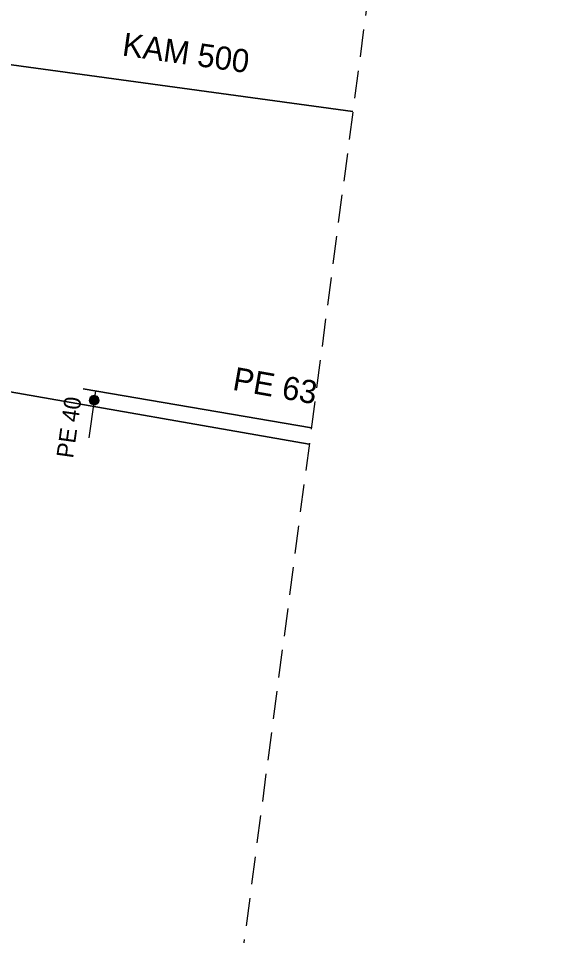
# Model space of a CAD drawing. Extents: x -867121 to -866743, y -1014362 to -1014088.
# Drawn here: x -866767.71 to -866742.8, y -1014225.88 to -1014182.35 of the extents above; entities that cross this region are included whole.
import ezdxf

# ---------------------------------------------------------------- set-up
doc = ezdxf.new("R2010")
doc.units = 0
doc.header["$LTSCALE"] = 0.44
doc.linetypes.add('MEDIUM_DASHED', pattern=[4.5, 3, -1.5])
for name, color, linetype, lineweight in [('1', 7, 'Continuous', 35), ('12', 7, 'Continuous', 13), ('21', 7, 'Continuous', 35), ('3', 7, 'Continuous', 25), ('62', 7, 'MEDIUM_DASHED', 25)]:
    doc.layers.add(name, color=color, linetype=linetype, lineweight=lineweight)

msp = doc.modelspace()

# ---------------------------------------------------------------- linework, layer by layer
at = {"layer": '1'}
for p, q in [((-866753.889, -1014202.559), (-866776.544, -1014198.596)), ((-866753.786, -1014201.776), (-866764.627, -1014199.93))]:
    msp.add_line(p, q, dxfattribs=at)
at = {"layer": '12'}
for points in [[(-866763.874, -1014200.462), (-866763.88, -1014200.41), (-866763.897, -1014200.36), (-866763.926, -1014200.316), (-866763.963, -1014200.279), (-866764.008, -1014200.252), (-866764.058, -1014200.235), (-866764.111, -1014200.231), (-866764.163, -1014200.238), (-866764.212, -1014200.257), (-866764.255, -1014200.286), (-866764.291, -1014200.325), (-866764.317, -1014200.37), (-866764.333, -1014200.421), (-866764.336, -1014200.473), (-866764.328, -1014200.525), (-866764.308, -1014200.574), (-866764.277, -1014200.617), (-866764.238, -1014200.651), (-866764.192, -1014200.677), (-866764.141, -1014200.691), (-866764.088, -1014200.693), (-866764.037, -1014200.683), (-866763.989, -1014200.662), (-866763.946, -1014200.631), (-866763.912, -1014200.59), (-866763.888, -1014200.544), (-866763.875, -1014200.493)], [(-866763.904, -1014200.462), (-866763.91, -1014200.413), (-866763.927, -1014200.367), (-866763.955, -1014200.327), (-866763.992, -1014200.295), (-866764.036, -1014200.273), (-866764.084, -1014200.262), (-866764.133, -1014200.262), (-866764.179, -1014200.275), (-866764.223, -1014200.299), (-866764.259, -1014200.332), (-866764.286, -1014200.373), (-866764.302, -1014200.42), (-866764.306, -1014200.469), (-866764.299, -1014200.517), (-866764.28, -1014200.562), (-866764.25, -1014200.602), (-866764.212, -1014200.633), (-866764.168, -1014200.653), (-866764.12, -1014200.663), (-866764.071, -1014200.661), (-866764.024, -1014200.646), (-866763.981, -1014200.621), (-866763.946, -1014200.587), (-866763.921, -1014200.545), (-866763.907, -1014200.498)], [(-866763.934, -1014200.462), (-866763.94, -1014200.417), (-866763.956, -1014200.375), (-866763.985, -1014200.34), (-866764.021, -1014200.313), (-866764.063, -1014200.296), (-866764.108, -1014200.291), (-866764.152, -1014200.297), (-866764.194, -1014200.316), (-866764.228, -1014200.344), (-866764.255, -1014200.381), (-866764.272, -1014200.423), (-866764.276, -1014200.468), (-866764.269, -1014200.513), (-866764.25, -1014200.554), (-866764.221, -1014200.588), (-866764.184, -1014200.614), (-866764.141, -1014200.63), (-866764.096, -1014200.633), (-866764.051, -1014200.625), (-866764.011, -1014200.605), (-866763.977, -1014200.576), (-866763.951, -1014200.538), (-866763.937, -1014200.495)], [(-866763.964, -1014200.462), (-866763.968, -1014200.421), (-866763.987, -1014200.384), (-866764.014, -1014200.353), (-866764.049, -1014200.332), (-866764.089, -1014200.321), (-866764.13, -1014200.323), (-866764.169, -1014200.336), (-866764.203, -1014200.36), (-866764.228, -1014200.392), (-866764.243, -1014200.43), (-866764.245, -1014200.471), (-866764.238, -1014200.511), (-866764.218, -1014200.547), (-866764.189, -1014200.576), (-866764.152, -1014200.595), (-866764.112, -1014200.603), (-866764.071, -1014200.599), (-866764.032, -1014200.584), (-866764, -1014200.558), (-866763.978, -1014200.524), (-866763.965, -1014200.485)], [(-866763.994, -1014200.462), (-866763.999, -1014200.426), (-866764.017, -1014200.394), (-866764.043, -1014200.369), (-866764.076, -1014200.354), (-866764.113, -1014200.351), (-866764.147, -1014200.359), (-866764.179, -1014200.379), (-866764.201, -1014200.407), (-866764.215, -1014200.441), (-866764.215, -1014200.478), (-866764.204, -1014200.513), (-866764.183, -1014200.542), (-866764.152, -1014200.563), (-866764.118, -1014200.573), (-866764.081, -1014200.571), (-866764.047, -1014200.557), (-866764.02, -1014200.534), (-866764, -1014200.502), (-866763.994, -1014200.467)], [(-866764.024, -1014200.462), (-866764.029, -1014200.431), (-866764.046, -1014200.405), (-866764.071, -1014200.388), (-866764.102, -1014200.381), (-866764.133, -1014200.385), (-866764.16, -1014200.402), (-866764.178, -1014200.426), (-866764.186, -1014200.457), (-866764.182, -1014200.487), (-866764.167, -1014200.515), (-866764.142, -1014200.534), (-866764.113, -1014200.543), (-866764.081, -1014200.54), (-866764.054, -1014200.526), (-866764.034, -1014200.502), (-866764.024, -1014200.473)], [(-866764.054, -1014200.462), (-866764.059, -1014200.438), (-866764.076, -1014200.42), (-866764.098, -1014200.411), (-866764.123, -1014200.414), (-866764.144, -1014200.428), (-866764.155, -1014200.45), (-866764.155, -1014200.475), (-866764.142, -1014200.496), (-866764.123, -1014200.51), (-866764.098, -1014200.513), (-866764.075, -1014200.504), (-866764.059, -1014200.486)], [(-866764.084, -1014200.462), (-866764.089, -1014200.447), (-866764.103, -1014200.441), (-866764.119, -1014200.445), (-866764.125, -1014200.459), (-866764.122, -1014200.474), (-866764.108, -1014200.483), (-866764.093, -1014200.48), (-866764.084, -1014200.468)]]:
    msp.add_lwpolyline(points, close=True, dxfattribs=at)
at = {"layer": '21'}
msp.add_line((-866751.815, -1014186.769), (-866777.346, -1014183.28), dxfattribs=at)
at = {"layer": '3'}
msp.add_lwpolyline([(-866764.048, -1014200.029), (-866764.105, -1014200.462), (-866764.361, -1014202.251)], dxfattribs=at)
at = {"layer": '62'}
msp.add_lwpolyline([(-867067.961, -1014088.34), (-866742.796, -1014118.083), (-866768.922, -1014317.041), (-866980.741, -1014362.46), (-867121.419, -1014295.739)], close=True, dxfattribs=at)

# ---------------------------------------------------------------- texts
at = {"layer": '1'}
for s, height, rotation, p in [('KAM 500 ', 1.1, 352, (-866762.814, -1014184.105)), ('PE 63 ', 1.1, 350, (-866757.573, -1014199.967)), ('PE 40 ', 0.8, 82, (-866765.11, -1014203.251))]:
    msp.add_text(s, height=height, rotation=rotation, dxfattribs=at).set_placement(p)

doc.saveas('drawing.dxf')
